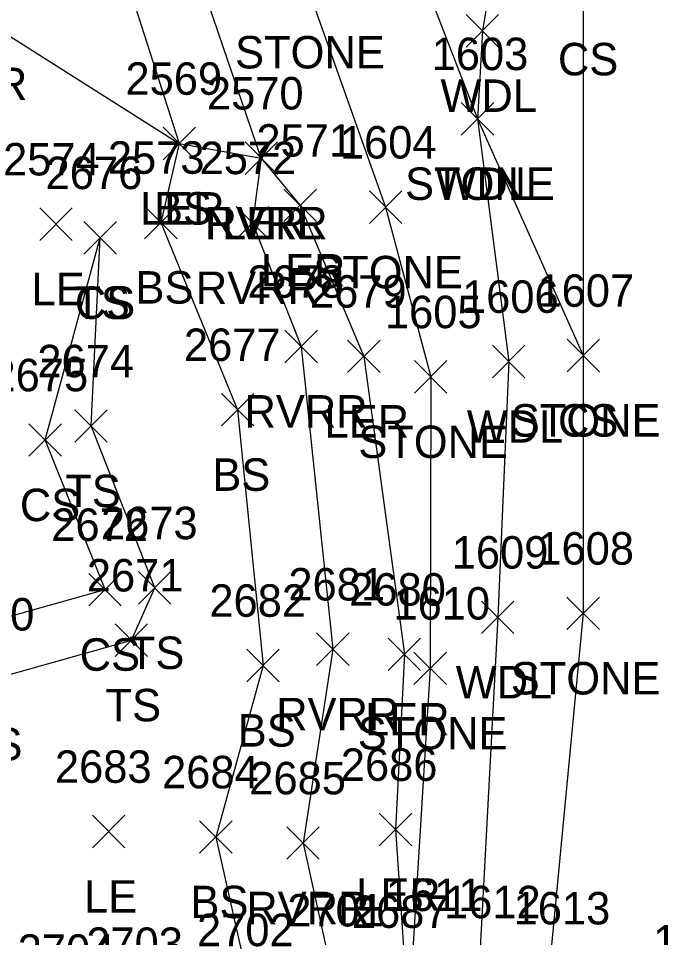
# Model space of a CAD drawing. Extents: x 1512665 to 1513714, y 110636 to 112816.
# Drawn here: x 1513066.2 to 1513105.8, y 110851.6 to 110908.3 of the extents above; entities that cross this region are included whole.
import ezdxf

# ---------------------------------------------------------------- set-up
doc = ezdxf.new("R2010")
doc.units = 0
for name, color, linetype in [('L_A', 7, 'Continuous'), ('L_I', 7, 'Continuous'), ('L_TIC', 7, 'Continuous'), ('LARO', 7, 'Continuous'), ('LASF', 7, 'Continuous'), ('LAWA', 7, 'Continuous'), ('LAWE', 7, 'Continuous'), ('LELB', 7, 'Continuous')]:
    doc.layers.add(name, color=color, linetype=linetype)

msp = doc.modelspace()

# ---------------------------------------------------------------- linework, layer by layer
at = {"layer": 'L_TIC'}
for points in [[(1513093.752, 110906.488), (1513095.752, 110908.488)], [(1513095.752, 110906.488), (1513093.752, 110908.488)], [(1513093.448, 110901.065), (1513095.448, 110903.065)], [(1513095.448, 110901.065), (1513093.448, 110903.065)], [(1513093.448, 110901.065), (1513095.448, 110903.065)], [(1513095.448, 110901.065), (1513093.448, 110903.065)], [(1513075.095, 110899.544), (1513077.095, 110901.544)], [(1513077.095, 110899.544), (1513075.095, 110901.544)], [(1513075.095, 110899.544), (1513077.095, 110901.544)], [(1513077.095, 110899.544), (1513075.095, 110901.544)], [(1513080.142, 110898.638), (1513082.142, 110900.638)], [(1513082.142, 110898.638), (1513080.142, 110900.638)], [(1513080.142, 110898.638), (1513082.142, 110900.638)], [(1513082.142, 110898.638), (1513080.142, 110900.638)], [(1513080.142, 110898.638), (1513082.142, 110900.638)], [(1513082.142, 110898.638), (1513080.142, 110900.638)], [(1513082.533, 110895.731), (1513084.533, 110897.731)], [(1513084.533, 110895.731), (1513082.533, 110897.731)], [(1513087.797, 110895.617), (1513089.797, 110897.617)], [(1513089.797, 110895.617), (1513087.797, 110897.617)], [(1513067.506, 110894.574), (1513069.506, 110896.574)], [(1513069.506, 110894.574), (1513067.506, 110896.574)], [(1513073.956, 110894.677), (1513075.956, 110896.677)], [(1513075.956, 110894.677), (1513073.956, 110896.677)], [(1513079.601, 110894.655), (1513081.601, 110896.655)], [(1513081.601, 110894.655), (1513079.601, 110896.655)], [(1513070.224, 110893.733), (1513072.224, 110895.733)], [(1513072.224, 110893.733), (1513070.224, 110895.733)], [(1513070.224, 110893.733), (1513072.224, 110895.733)], [(1513072.224, 110893.733), (1513070.224, 110895.733)], [(1513082.596, 110887.037), (1513084.596, 110889.037)], [(1513084.596, 110887.037), (1513082.596, 110889.037)], [(1513086.45, 110886.426), (1513088.45, 110888.426)], [(1513088.45, 110886.426), (1513086.45, 110888.426)], [(1513095.371, 110886.106), (1513097.371, 110888.106)], [(1513097.371, 110886.106), (1513095.371, 110888.106)], [(1513099.963, 110886.481), (1513101.963, 110888.481)], [(1513101.963, 110886.481), (1513099.963, 110888.481)], [(1513099.963, 110886.481), (1513101.963, 110888.481)], [(1513101.963, 110886.481), (1513099.963, 110888.481)], [(1513090.571, 110885.161), (1513092.571, 110887.161)], [(1513092.571, 110885.161), (1513090.571, 110887.161)], [(1513078.686, 110883.14), (1513080.686, 110885.14)], [(1513080.686, 110883.14), (1513078.686, 110885.14)], [(1513069.662, 110882.136), (1513071.662, 110884.136)], [(1513071.662, 110882.136), (1513069.662, 110884.136)], [(1513066.839, 110881.274), (1513068.839, 110883.274)], [(1513068.839, 110881.274), (1513066.839, 110883.274)], [(1513070.52, 110872.054), (1513072.52, 110874.054)], [(1513072.52, 110872.054), (1513070.52, 110874.054)], [(1513073.579, 110872.16), (1513075.579, 110874.16)], [(1513075.579, 110872.16), (1513073.579, 110874.16)], [(1513094.693, 110870.347), (1513096.693, 110872.347)], [(1513096.693, 110870.347), (1513094.693, 110872.347)], [(1513099.956, 110870.594), (1513101.956, 110872.594)], [(1513101.956, 110870.594), (1513099.956, 110872.594)], [(1513072.142, 110868.938), (1513074.142, 110870.938)], [(1513074.142, 110868.938), (1513072.142, 110870.938)], [(1513084.549, 110868.383), (1513086.549, 110870.383)], [(1513086.549, 110868.383), (1513084.549, 110870.383)], [(1513088.949, 110868.067), (1513090.949, 110870.067)], [(1513090.949, 110868.067), (1513088.949, 110870.067)], [(1513080.251, 110867.379), (1513082.251, 110869.379)], [(1513082.251, 110867.379), (1513080.251, 110869.379)], [(1513090.538, 110867.206), (1513092.538, 110869.206)], [(1513092.538, 110867.206), (1513090.538, 110869.206)], [(1513070.744, 110857.148), (1513072.744, 110859.148)], [(1513072.744, 110857.148), (1513070.744, 110859.148)], [(1513088.4, 110857.27), (1513090.4, 110859.27)], [(1513090.4, 110857.27), (1513088.4, 110859.27)], [(1513077.341, 110856.81), (1513079.341, 110858.81)], [(1513079.341, 110856.81), (1513077.341, 110858.81)], [(1513082.709, 110856.437), (1513084.709, 110858.437)], [(1513084.709, 110856.437), (1513082.709, 110858.437)]]:
    msp.add_lwpolyline(points, dxfattribs=at)
at = {"layer": 'LARO'}
msp.add_lwpolyline([(1513062.377, 110914.721), (1513063.95, 110908.226), (1513076.095, 110900.544), (1513081.142, 110899.638), (1513083.533, 110896.731), (1513087.45, 110887.426), (1513089.949, 110869.067), (1513089.4, 110858.27), (1513090.026, 110849.208)], dxfattribs=at)
at = {"layer": 'LASF'}
for points in [[(1513082.572, 110964.477), (1513082.926, 110956.923), (1513079.738, 110953.902), (1513075.318, 110941.648), (1513074.533, 110936.033), (1513075.492, 110928.453), (1513086.832, 110921.767), (1513094.448, 110902.065), (1513100.963, 110887.481), (1513100.956, 110871.594), (1513098.848, 110849.423), (1513096.994, 110839.108)], [(1513074.699, 110918.552), (1513083.984, 110910.167), (1513088.797, 110896.617), (1513091.571, 110886.161), (1513091.538, 110868.206), (1513090.42, 110850.246), (1513096.994, 110839.108)]]:
    msp.add_lwpolyline(points, dxfattribs=at)
at = {"layer": 'LAWA'}
msp.add_lwpolyline([(1513113.578, 110922.99), (1513102.637, 110919.327), (1513097.199, 110922.304), (1513094.752, 110907.488), (1513094.448, 110902.065), (1513096.371, 110887.106), (1513095.693, 110871.347), (1513094.563, 110849.806), (1513096.994, 110839.108), (1513095.313, 110829.256)], dxfattribs=at)
at = {"layer": 'LAWE'}
for points in [[(1513081.142, 110899.638), (1513074.699, 110918.552)], [(1513081.142, 110899.638), (1513080.601, 110895.655), (1513083.596, 110888.037), (1513085.549, 110869.383), (1513083.709, 110857.437), (1513085.514, 110849.299), (1513080.439, 110838.078), (1513082.504, 110823.737), (1513080.964, 110819.753), (1513079.852, 110819.375), (1513080.565, 110816.05), (1513078.532, 110813.009), (1513078.61, 110806.47), (1513077.103, 110805.033), (1513075.916, 110802.317), (1513075.155, 110800.449), (1513074.311, 110797.361)]]:
    msp.add_lwpolyline(points, dxfattribs=at)
at = {"layer": 'LELB'}
for points in [[(1513050.573, 111091.961), (1513051.197, 111062.89), (1513055.33, 111032.784), (1513054.275, 111000.379), (1513059.508, 110973.721), (1513056.822, 110953.439), (1513063.6, 110941.615), (1513067.127, 110927.728), (1513070.914, 110916.685), (1513076.095, 110900.544), (1513074.956, 110895.677), (1513079.686, 110884.14), (1513081.251, 110868.379), (1513078.341, 110857.81), (1513080.523, 110848.083), (1513078.461, 110838.385), (1513078.11, 110823.814), (1513078.515, 110819.273), (1513078.06, 110816.046), (1513076.988, 110814.704), (1513073.485, 110811.479), (1513073.805, 110795.938), (1513074.513, 110793.139), (1513077.432, 110790.977)], [(1513074.286, 111090.888), (1513073.455, 111069.861), (1513077.055, 111044.988), (1513079.127, 111026.942), (1513081.175, 111003.037), (1513084.439, 110991.205), (1513085.922, 110971.631), (1513087.543, 110964.28), (1513094.931, 110950.257), (1513100.487, 110942.417), (1513104.747, 110930.663), (1513102.637, 110919.327), (1513100.961, 110909.74), (1513100.963, 110887.481)], [(1513056.876, 110868.998), (1513062.324, 110870.473), (1513071.52, 110873.054), (1513067.839, 110882.274), (1513071.224, 110894.733)], [(1513058.241, 110864.438), (1513060.286, 110866.336), (1513064.615, 110867.532), (1513073.142, 110869.938), (1513074.579, 110873.16), (1513070.662, 110883.136), (1513071.224, 110894.733)]]:
    msp.add_lwpolyline(points, dxfattribs=at)

# ---------------------------------------------------------------- texts
at = {"layer": 'L_A'}
for s, p in [('STONE', (1513079.528, 110905.167)), ('CS', (1513099.402, 110904.74)), ('LER', (1513061.532, 110903.226)), ('WDL', (1513092.169, 110902.488)), ('STONE', (1513089.992, 110897.065)), ('WDL', (1513091.866, 110897.065)), ('LER', (1513073.678, 110895.544)), ('BS', (1513074.536, 110895.544)), ('RVRR', (1513077.654, 110894.638)), ('RVRL', (1513077.709, 110894.638)), ('LER', (1513078.725, 110894.638)), ('LER', (1513081.116, 110891.731)), ('STONE', (1513084.34, 110891.617)), ('LE', (1513066.994, 110890.574)), ('BS', (1513073.397, 110890.677)), ('RVRR', (1513077.113, 110890.655)), ('TS', (1513069.633, 110889.733)), ('CS', (1513069.665, 110889.733)), ('RVRR', (1513080.107, 110883.037)), ('LER', (1513085.033, 110882.426)), ('WDL', (1513093.788, 110882.106)), ('STONE', (1513096.506, 110882.481)), ('CS', (1513099.404, 110882.481)), ('STONE', (1513087.114, 110881.161)), ('BS', (1513078.127, 110879.14)), ('TS', (1513069.072, 110878.136)), ('CS', (1513066.28, 110877.274)), ('CS', (1513069.961, 110868.054)), ('TS', (1513072.989, 110868.16)), ('WDL', (1513093.11, 110866.347)), ('STONE', (1513096.5, 110866.594)), ('TS', (1513071.551, 110864.938)), ('RVRR', (1513082.061, 110864.383)), ('LER', (1513087.531, 110864.067)), ('BS', (1513079.692, 110863.379)), ('STONE', (1513087.081, 110863.206)), ('TS', (1513063.024, 110862.532)), ('LE', (1513070.232, 110853.148)), ('LER', (1513086.982, 110853.27)), ('BS', (1513076.782, 110852.81)), ('RVRR', (1513080.221, 110852.437))]:
    msp.add_text(s, height=2, dxfattribs=at).set_placement(p)
at = {"layer": 'L_I'}
for s, p in [('1603', (1513091.629, 110905.065)), ('1603', (1513091.629, 110905.065)), ('2569', (1513072.78, 110903.544)), ('2569', (1513072.78, 110903.544)), ('2570', (1513077.795, 110902.638)), ('2570', (1513077.795, 110902.638)), ('2570', (1513077.795, 110902.638)), ('2571', (1513080.841, 110899.731)), ('1604', (1513085.978, 110899.617)), ('2574', (1513065.246, 110898.574)), ('2573', (1513071.696, 110898.677)), ('2572', (1513077.341, 110898.655)), ('2676', (1513067.862, 110897.733)), ('2676', (1513067.862, 110897.733)), ('2678', (1513080.288, 110891.037)), ('1607', (1513098.144, 110890.481)), ('1607', (1513098.144, 110890.481)), ('2679', (1513084.135, 110890.426)), ('1606', (1513093.497, 110890.106)), ('1605', (1513088.752, 110889.161)), ('2677', (1513076.379, 110887.14)), ('2674', (1513067.355, 110886.136)), ('2675', (1513064.532, 110885.274)), ('2672', (1513068.213, 110876.054)), ('2673', (1513071.272, 110876.16)), ('1609', (1513092.866, 110874.347)), ('1608', (1513098.137, 110874.594)), ('2671', (1513070.402, 110872.938)), ('2681', (1513082.809, 110872.383)), ('2680', (1513086.555, 110872.067)), ('2682', (1513077.944, 110871.379)), ('1610', (1513089.278, 110871.206)), ('2670', (1513061.221, 110870.532)), ('2683', (1513068.437, 110861.148)), ('2686', (1513086.037, 110861.27)), ('2684', (1513075.033, 110860.81)), ('2685', (1513080.402, 110860.437)), ('1611', (1513088.814, 110853.246)), ('1612', (1513092.39, 110852.806)), ('2701', (1513082.742, 110852.299)), ('2687', (1513086.719, 110852.208)), ('1613', (1513096.675, 110852.423)), ('2702', (1513077.184, 110851.083)), ('1624', (1513105.264, 110850.38)), ('2704', (1513066.143, 110849.813)), ('2703', (1513070.368, 110850.236))]:
    msp.add_text(s, height=2, dxfattribs=at).set_placement(p)

doc.saveas('drawing.dxf')
